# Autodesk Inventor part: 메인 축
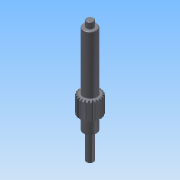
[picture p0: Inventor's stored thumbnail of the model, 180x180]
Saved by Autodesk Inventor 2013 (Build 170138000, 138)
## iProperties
Created: 2016-02
Part Number: 메인 축
Material: 강철, 연강
Document SubType Name: Modeling
Categories: <?xml version="1.0" encoding="UTF-16"?> <MemberInstance><Categories><FamilyTemplate><FamilyTemplateParameter ValueType="xs:double" Id="1" ObjectReferenceKey="da
Density: 1 g/cm^3
Mass: 23.8554 g
Surface Area: 82.0529 cm^2
Volume: 23.8554 cm^3
Author: mdu
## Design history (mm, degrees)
sketch "Sketch1"
  geometry: C1 r 12 at (0, 0)
  constraints: 1 centre point
  dimensions: "d0" = 24 diameter of C1 (= da_da)
extrude "Extrusion1" new body sketch "Sketch1" distance "d1" = 20 (= da_b); taper "d2" = 0 deg
workplane "Work Plane2"
feature "피치 지름" dims "d4" = 10, "d5" = 0
workplane "Work Plane8"
workplane "Work Plane9"
chamfer "모따기1" distance "d49" = 1; stored, may be unused: second distance "d50" = 2, angle "d51" = 45 deg
sketch "스케치3"
  geometry: C1 r 7.5 at (0, 0); 1 further point
  constraints: 1 centre point, 1 coincident
  dimensions: "d52" = 15 diameter of C1
extrude "돌출2" join sketch "스케치3" distance "d53" = 66; taper "d54" = 0 deg
sketch "스케치4"
  geometry: C1 r 4 at (0, 0); 1 further point
  constraints: 1 centre point, 1 coincident
  dimensions: "d55" = 8 diameter of C1
extrude "돌출3" join sketch "스케치4" distance "d56" = 7; taper "d57" = 0 deg
sketch "스케치5"
  geometry: C1 r 7.5 at (0, 0) reference; C2 r 7.5 at (0, 0) reference; 1 further point
extrude "돌출4" join sketch "스케치5" distance "d62" = 16; taper "d63" = 0 deg
sketch "스케치6"
  geometry: C1 r 4 at (0, 0); 1 further point
  constraints: 1 centre point, 1 coincident
  dimensions: "d64" = 8 diameter of C1
extrude "돌출5" join sketch "스케치6" distance "d65" = 30; taper "d66" = 0 deg
chamfer "모따기2" distance "d58" = 0.5; stored, may be unused: second distance "d59" = 2, angle "d60" = 45 deg
fillet "모깎기1" dims "d61" = 0.5
feature "스퍼 기어" dims "da_b" = 20, "da_d" = 22, "da_aw" = 31, "da_da" = 24, "da_df" = 19.5, "da_dw" = 22, angle "da_beta" = 0 deg, "da_lefttooth" = 0, "da_righttooth" = 0
sketch "스케치7" dims "d68" = 18
  geometry: C1 r 0.25 at (0, -9); 2 further points
  constraints: 2 vertical alignment, 1 centre point, 1 coincident, 2 other
  dimensions: "d67" = 0.5 diameter of C1
extrude "돌출6" join sketch "스케치7" distance "d69" = 0.3; taper "d70" = 0 deg
body "Solid1"
sketch "Sketch2"
  geometry: C1 r 12 at (0, 0) reference; C2 r 11 at (0, 0)
  constraints: 1 centre point, 1 coincident
  dimensions: "d3" = 22 diameter of C2 (= da_dw)
body "Srf1"
node "투영된 루프1"
other parameters: "d16" = 31 (= da_aw), "d17" = 0, "d34" = 1.428 (computed from da_z), "d39" = 0, "d41" = 0, "d43" = 31 (= da_aw), "d46" = 31 (= da_aw), "d47" = 0, "d48" = 0
